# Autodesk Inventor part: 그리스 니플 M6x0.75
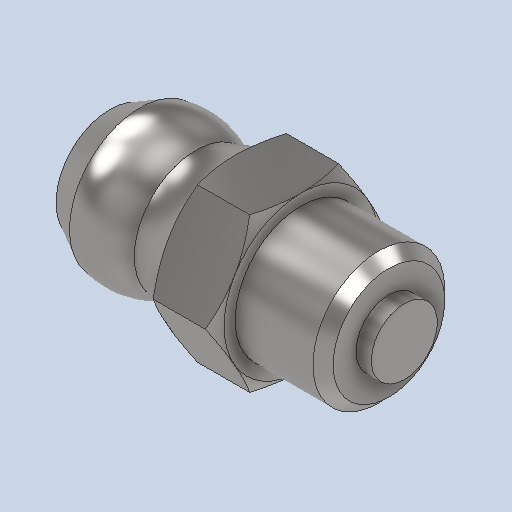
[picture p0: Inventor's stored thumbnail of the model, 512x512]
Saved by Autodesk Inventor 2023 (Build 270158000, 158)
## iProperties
Created: 2026-03
Part Number: 그리스 니플 M6x0.75
Material: 강철, 연강
Description: 윤활 니플, 원추 유형 A
Document SubType Name: Modeling
Designer: 4강의실
Density: 7.85 g/cm^3
Appearance: 기본값
Author: jhkim
Sending System: Autodesk Inventor 2026
Preprocessor: ST-DEVELOPER v20.1
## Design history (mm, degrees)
feature "Solid1"
node "솔리드1"
